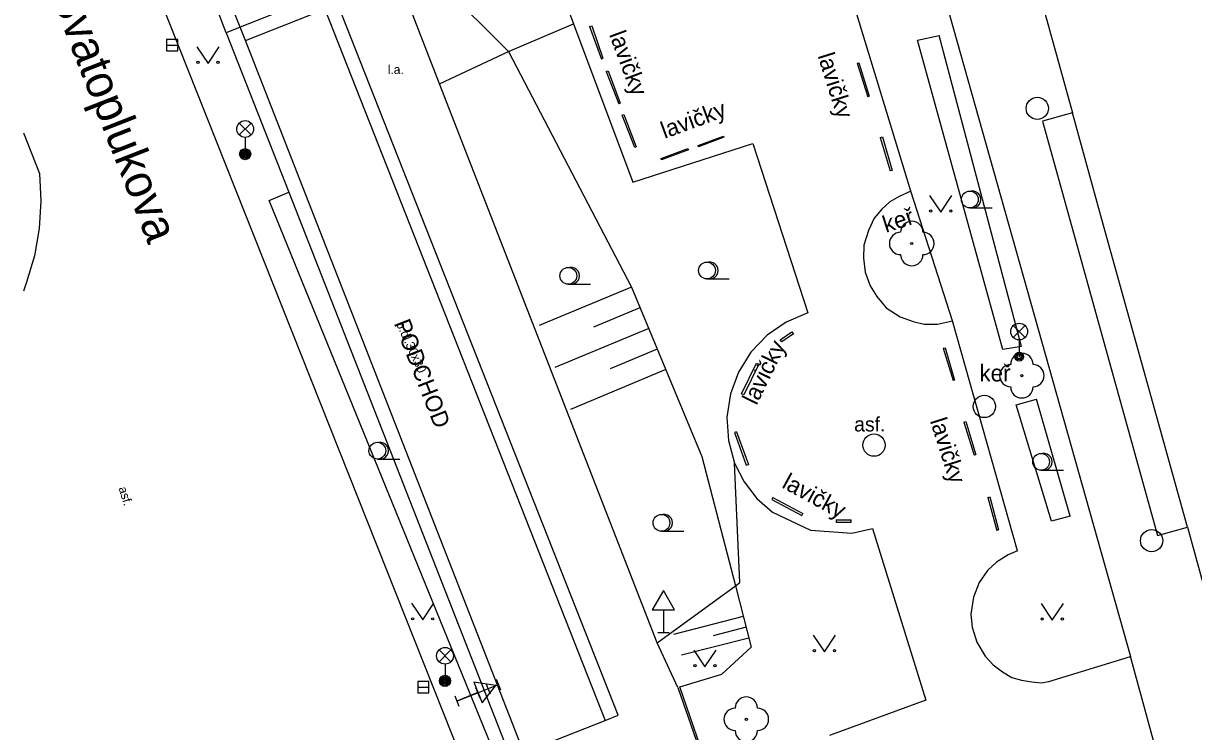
# Model space of a CAD drawing. Extents: x -595546 to -593986, y -1160845 to -1159202.
# Drawn here: x -595539.6 to -595487.2, y -1160276.7 to -1160245 of the extents above; entities that cross this region are included whole.
import ezdxf

# ---------------------------------------------------------------- set-up
doc = ezdxf.new("R2010")
doc.units = 0
for name, color, linetype in [('Level 22', 7, 'Continuous'), ('Level 25', 7, 'Continuous'), ('Level 27', 7, 'Continuous'), ('Level 33', 7, 'Continuous'), ('Level 34', 7, 'Continuous'), ('Level 36', 7, 'Continuous'), ('Nazvy ulic', 7, 'Continuous'), ('Specificka linie pasportu komunikaci', 7, 'Continuous'), ('TM - budovy zdene_ betonove - VP', 7, 'Continuous'), ('TM - chodniky - NP', 7, 'Continuous'), ('TM - chodniky - VP', 7, 'Continuous'), ('TM - horni hrana svahu', 7, 'Continuous'), ('TM - hranice souvisleho porostu (skupiny stromu_ kere)', 7, 'Continuous'), ('TM - komunikace - VP', 7, 'Continuous'), ('TM - lavicka', 7, 'Continuous'), ('TM - podezdivka plotu - VP', 7, 'Continuous'), ('TM - pomocna konstrukcni linie', 7, 'Continuous'), ('TM - popis objektu', 7, 'Continuous'), ('TM - popis povrchu', 7, 'Continuous'), ('TM - popis zelene', 7, 'Continuous'), ('TM - poznamka', 7, 'Continuous'), ('TM - rozhrani ploch obecne - VP', 7, 'Continuous'), ('TM - srafovani', 7, 'Continuous'), ('TM - zed operna - VP', 7, 'Continuous')]:
    doc.layers.add(name, color=color, linetype=linetype)

msp = doc.modelspace()

# ---------------------------------------------------------------- linework, layer by layer
at = {"layer": 'Level 22'}
for centre in [(-595499.8, -1160254.87), (-595494.87, -1160260.79), (-595507.21, -1160276.18)]:
    msp.add_circle(centre, 0.05, dxfattribs=at)
for centre, start, end in [((-595499.8, -1160254.37), 0, 180), ((-595500.3, -1160254.87), 90, 270), ((-595499.3, -1160254.87), 270, 90), ((-595499.8, -1160255.37), 180, 0), ((-595494.87, -1160260.29), 0, 180), ((-595495.37, -1160260.79), 90, 270), ((-595494.37, -1160260.79), 270, 90), ((-595494.87, -1160261.29), 180, 0), ((-595507.21, -1160275.68), 0, 180), ((-595507.71, -1160276.18), 90, 270), ((-595506.71, -1160276.18), 270, 90), ((-595507.21, -1160276.68), 180, 0)]:
    msp.add_arc(centre, 0.5, start, end, dxfattribs=at)
at = {"layer": 'Level 25'}
for centre, radius in [((-595529.65, -1160250.87), 0.25), ((-595529.65, -1160250.87), 0.2), ((-595529.65, -1160250.87), 0.15), ((-595529.65, -1160250.87), 0.1), ((-595529.65, -1160250.87), 0.05), ((-595520.7, -1160274.46), 0.25), ((-595520.7, -1160274.46), 0.2), ((-595520.7, -1160274.46), 0.15), ((-595520.7, -1160274.46), 0.1), ((-595520.7, -1160274.46), 0.05)]:
    msp.add_circle(centre, radius, dxfattribs=at)
at = {"layer": 'Level 27'}
for p, q in [((-595533.17, -1160245.99), (-595532.67, -1160245.99)), ((-595521.92, -1160274.74), (-595521.42, -1160274.74))]:
    msp.add_line(p, q, dxfattribs=at)
for points in [[(-595533.17, -1160246.24), (-595532.67, -1160246.24), (-595532.67, -1160245.74), (-595533.17, -1160245.74)], [(-595521.92, -1160274.99), (-595521.42, -1160274.99), (-595521.42, -1160274.49), (-595521.92, -1160274.49)]]:
    msp.add_lwpolyline(points, close=True, dxfattribs=at)
for centre in [(-595494.18, -1160248.82), (-595496.55, -1160262.17), (-595501.49, -1160263.9), (-595489.06, -1160268.18)]:
    msp.add_circle(centre, 0.5, dxfattribs=at)
at = {"layer": 'Level 33'}
for p, q in [((-595529.915, -1160250.01), (-595529.385, -1160249.48)), ((-595529.915, -1160249.48), (-595529.385, -1160250.01)), ((-595529.65, -1160250.12), (-595529.65, -1160250.87)), ((-595495.255, -1160259.08), (-595494.725, -1160258.55)), ((-595495.255, -1160258.55), (-595494.725, -1160259.08)), ((-595494.99, -1160259.19), (-595494.99, -1160259.94)), ((-595520.965, -1160273.6), (-595520.435, -1160273.07)), ((-595520.965, -1160273.07), (-595520.435, -1160273.6)), ((-595520.7, -1160273.71), (-595520.7, -1160274.46)), ((-595520.17, -1160275.36), (-595518.311, -1160274.622)), ((-595519.333, -1160274.759), (-595519.148, -1160275.223)), ((-595518.868, -1160274.574), (-595518.684, -1160275.039)), ((-595518.403, -1160274.389), (-595518.219, -1160274.854)), ((-595520.262, -1160275.128), (-595520.078, -1160275.592))]:
    msp.add_line(p, q, dxfattribs=at)
for centre, radius in [((-595529.65, -1160249.745), 0.375), ((-595529.65, -1160250.87), 0.2), ((-595529.65, -1160250.87), 0.145), ((-595529.65, -1160250.87), 0.0876), ((-595494.99, -1160258.815), 0.375), ((-595494.99, -1160259.94), 0.2), ((-595494.99, -1160259.94), 0.145), ((-595494.99, -1160259.94), 0.0876), ((-595520.7, -1160273.335), 0.375), ((-595520.7, -1160274.46), 0.2), ((-595520.7, -1160274.46), 0.145), ((-595520.7, -1160274.46), 0.0876)]:
    msp.add_circle(centre, radius, dxfattribs=at)
at = {"layer": 'Level 34'}
for p, q in [((-595510.92, -1160271.272), (-595510.92, -1160272.29)), ((-595511.17, -1160272.29), (-595510.67, -1160272.29)), ((-595520.262, -1160275.128), (-595520.078, -1160275.592)), ((-595519.224, -1160274.984), (-595520.17, -1160275.36))]:
    msp.add_line(p, q, dxfattribs=at)
for points in [[(-595511.42, -1160271.272), (-595510.42, -1160271.272), (-595510.92, -1160270.406)], [(-595519.408, -1160274.52), (-595519.039, -1160275.449), (-595518.419, -1160274.665)]]:
    msp.add_lwpolyline(points, close=True, dxfattribs=at)
at = {"layer": 'Level 36'}
for p, q in [((-595497.2, -1160253.275), (-595496.2, -1160253.275)), ((-595515.18, -1160256.695), (-595514.18, -1160256.695)), ((-595508.97, -1160256.455), (-595507.97, -1160256.455)), ((-595523.73, -1160264.525), (-595522.73, -1160264.525)), ((-595494.01, -1160265.025), (-595493.01, -1160265.025)), ((-595511.01, -1160267.755), (-595510.01, -1160267.755))]:
    msp.add_line(p, q, dxfattribs=at)
for points in [[(-595531.81, -1160246.06), (-595531.31, -1160246.81), (-595530.81, -1160246.06)], [(-595499, -1160252.72), (-595498.5, -1160253.47), (-595498, -1160252.72)], [(-595522.2, -1160270.98), (-595521.7, -1160271.73), (-595521.2, -1160270.98)], [(-595494.01, -1160270.99), (-595493.51, -1160271.74), (-595493.01, -1160270.99)], [(-595504.21, -1160272.41), (-595503.71, -1160273.16), (-595503.21, -1160272.41)], [(-595509.56, -1160273.08), (-595509.06, -1160273.83), (-595508.56, -1160273.08)]]:
    msp.add_lwpolyline(points, dxfattribs=at)
for centre, radius in [((-595531.76, -1160246.76), 0.05), ((-595530.861, -1160246.76), 0.05), ((-595497.2, -1160252.9), 0.375), ((-595498.95, -1160253.42), 0.05), ((-595498.051, -1160253.42), 0.05), ((-595508.97, -1160256.08), 0.375), ((-595515.18, -1160256.32), 0.375), ((-595523.73, -1160264.15), 0.375), ((-595494.01, -1160264.65), 0.375), ((-595511.01, -1160267.38), 0.375), ((-595522.15, -1160271.68), 0.05), ((-595521.251, -1160271.68), 0.05), ((-595493.96, -1160271.69), 0.05), ((-595493.061, -1160271.69), 0.05), ((-595504.16, -1160273.11), 0.05), ((-595503.261, -1160273.11), 0.05), ((-595509.51, -1160273.78), 0.05), ((-595508.611, -1160273.78), 0.05)]:
    msp.add_circle(centre, radius, dxfattribs=at)
for centre in [(-595497.075, -1160252.9), (-595508.845, -1160256.08), (-595515.055, -1160256.32), (-595523.605, -1160264.15), (-595493.885, -1160264.65), (-595510.885, -1160267.38)]:
    msp.add_arc(centre, 0.375, 260.4059, 99.5941, dxfattribs=at)
at = {"layer": 'Specificka linie pasportu komunikaci'}
for points in [[(-595487.46, -1160267.58), (-595491.21, -1160254.07), (-595492.61, -1160249.02)], [(-595497.98, -1160258.34), (-595498.488, -1160256.755), (-595499.84, -1160252.53)], [(-595488.38, -1160279.33), (-595490.01, -1160273.36)]]:
    msp.add_lwpolyline(points, dxfattribs=at)
at = {"layer": 'TM - budovy zdene_ betonove - VP'}
for points in [[(-595493.98, -1160244.06), (-595492.61, -1160249.02)], [(-595492.61, -1160249.02), (-595493.95, -1160249.4)], [(-595493.95, -1160249.4), (-595488.8, -1160267.95)], [(-595488.8, -1160267.95), (-595487.46, -1160267.58)], [(-595487.46, -1160267.58), (-595486.01, -1160272.85)]]:
    msp.add_lwpolyline(points, dxfattribs=at)
at = {"layer": 'TM - chodniky - NP'}
for points in [[(-595529.87, -1160245.18), (-595532.21, -1160239.27)], [(-595529.63, -1160245.78), (-595529.87, -1160245.18)]]:
    msp.add_lwpolyline(points, dxfattribs=at)
at = {"layer": 'TM - chodniky - VP'}
for points in [[(-595500.77, -1160235.2), (-595490.01, -1160273.36)], [(-595517.54, -1160238.05), (-595514.94, -1160245.03)], [(-595530.5, -1160245.43), (-595532.76, -1160239.49)], [(-595520.94, -1160247.72), (-595523.8, -1160240.35)], [(-595499.84, -1160252.53), (-595502.96, -1160242.29)], [(-595514.94, -1160245.03), (-595512.29, -1160252.13), (-595506.91, -1160250.4), (-595504.45, -1160257.98)], [(-595511.2, -1160272.76), (-595520.94, -1160247.72)], [(-595499.84, -1160252.53), (-595500.36, -1160252.76), (-595500.78, -1160253.01), (-595501.14, -1160253.34), (-595501.48, -1160253.74), (-595501.74, -1160254.29), (-595501.94, -1160254.95), (-595501.96, -1160255.53), (-595501.89, -1160256.16), (-595501.67, -1160256.76), (-595501.36, -1160257.25), (-595500.94, -1160257.75), (-595500.32, -1160258.15), (-595499.74, -1160258.36), (-595499.25, -1160258.48), (-595498.65, -1160258.48), (-595497.98, -1160258.34)], [(-595504.45, -1160257.98), (-595505.42, -1160258.39), (-595506.28, -1160258.98), (-595507.01, -1160259.74), (-595507.56, -1160260.63), (-595507.92, -1160261.61), (-595508.08, -1160262.65), (-595508.01, -1160263.7), (-595507.74, -1160264.71)], [(-595495.06, -1160268.63), (-595497.98, -1160258.34)], [(-595507.74, -1160264.71), (-595507.31, -1160265.55), (-595506.74, -1160266.29), (-595506.03, -1160266.91), (-595504.34, -1160267.71), (-595502.48, -1160267.84), (-595501.56, -1160267.64)], [(-595501.56, -1160267.64), (-595499.17, -1160275.32), (-595503.49, -1160276.91)], [(-595495.06, -1160268.63), (-595495.49, -1160268.82), (-595496, -1160269.14), (-595496.41, -1160269.51), (-595496.78, -1160270.06), (-595497.04, -1160270.71), (-595497.16, -1160271.47), (-595497.09, -1160272.05), (-595496.88, -1160272.72), (-595496.51, -1160273.35), (-595496.15, -1160273.74), (-595495.74, -1160274.06), (-595495.32, -1160274.3), (-595494.89, -1160274.42), (-595494.43, -1160274.5), (-595494, -1160274.54), (-595493.66, -1160274.48)], [(-595510.27, -1160274.76), (-595511.2, -1160272.76)], [(-595493.66, -1160274.48), (-595490.01, -1160273.36)], [(-595510.27, -1160274.76), (-595508.87, -1160278.78)]]:
    msp.add_lwpolyline(points, dxfattribs=at)
at = {"layer": 'TM - horni hrana svahu'}
for points in [[(-595523.8, -1160240.35), (-595517.86, -1160246.27)], [(-595517.86, -1160246.27), (-595512.35, -1160256.83), (-595509.2, -1160264.41), (-595507.7, -1160270.2)], [(-595507.7, -1160270.2), (-595506.99, -1160272.95), (-595508.3, -1160274.16)]]:
    msp.add_lwpolyline(points, dxfattribs=at)
at = {"layer": 'TM - hranice souvisleho porostu (skupiny stromu_ kere)'}
for points in [[(-595517.86, -1160246.27), (-595514.94, -1160245.03)], [(-595494.88, -1160259.48), (-595495.72, -1160259.62), (-595499.55, -1160245.76), (-595498.57, -1160245.55)], [(-595494.88, -1160259.48), (-595498.57, -1160245.55)], [(-595520.94, -1160247.72), (-595517.86, -1160246.27)], [(-595528.58, -1160252.94), (-595527.7, -1160252.58)], [(-595514.08, -1160288.52), (-595528.58, -1160252.94)], [(-595492.71, -1160267.08), (-595493.54, -1160267.3), (-595495.13, -1160262.09), (-595494.22, -1160261.84)], [(-595492.71, -1160267.08), (-595494.22, -1160261.84)]]:
    msp.add_lwpolyline(points, dxfattribs=at)
at = {"layer": 'TM - komunikace - VP'}
for points in [[(-595503.44, -1160319.53), (-595534.32, -1160241.75)], [(-595539.58, -1160249.921), (-595538.86, -1160251.73)], [(-595538.86, -1160251.73), (-595538.8, -1160252.96), (-595538.87, -1160254.2), (-595539.09, -1160255.42), (-595539.44, -1160256.6)], [(-595539.44, -1160256.6), (-595539.58, -1160257.005)]]:
    msp.add_lwpolyline(points, dxfattribs=at)
at = {"layer": 'TM - lavicka'}
for points in [[(-595514.23, -1160245.16), (-595513.69, -1160246.61)], [(-595502.24, -1160246.8), (-595501.77, -1160248.3)], [(-595513.49, -1160247.17), (-595512.91, -1160248.62)], [(-595512.2, -1160250.57), (-595512.77, -1160249.13)], [(-595508.21, -1160250.11), (-595509.35, -1160250.55)], [(-595501.21, -1160250.13), (-595500.76, -1160251.62)], [(-595509.8, -1160250.68), (-595511, -1160251.12)], [(-595505.1, -1160258.92), (-595505.62, -1160259.28)], [(-595498.39, -1160259.56), (-595497.94, -1160261.01)], [(-595506.65, -1160260.28), (-595507.32, -1160261.65)], [(-595497.47, -1160262.87), (-595497, -1160264.35)], [(-595507.65, -1160263.3), (-595507.11, -1160264.77)], [(-595506.02, -1160266.24), (-595504.68, -1160266.97)], [(-595496.4, -1160266.25), (-595495.99, -1160267.72)], [(-595503.18, -1160267.24), (-595502.52, -1160267.24)]]:
    msp.add_lwpolyline(points, dxfattribs=at)
at = {"layer": 'TM - podezdivka plotu - VP'}
for points in [[(-595529.63, -1160245.78), (-595526.08, -1160244.38)], [(-595526.08, -1160244.38), (-595513.53, -1160276.23)], [(-595517.17, -1160277.67), (-595529.63, -1160245.78)], [(-595513.53, -1160276.23), (-595512.95, -1160276)]]:
    msp.add_lwpolyline(points, dxfattribs=at)
at = {"layer": 'TM - pomocna konstrukcni linie'}
for points in [[(-595514.23, -1160245.16), (-595514.13, -1160245.13), (-595513.63, -1160246.57), (-595513.69, -1160246.61)], [(-595502.24, -1160246.8), (-595502.17, -1160246.78), (-595501.71, -1160248.28), (-595501.77, -1160248.3)], [(-595513.49, -1160247.17), (-595513.4, -1160247.14), (-595512.85, -1160248.59), (-595512.91, -1160248.62)], [(-595512.77, -1160249.13), (-595512.69, -1160249.1), (-595512.14, -1160250.54), (-595512.2, -1160250.57)], [(-595509.35, -1160250.55), (-595509.37, -1160250.49), (-595508.23, -1160250.06), (-595508.21, -1160250.11)], [(-595501.21, -1160250.13), (-595501.11, -1160250.1), (-595500.68, -1160251.6), (-595500.76, -1160251.62)], [(-595511, -1160251.12), (-595511.02, -1160251.06), (-595509.82, -1160250.62), (-595509.8, -1160250.68)], [(-595505.62, -1160259.28), (-595505.69, -1160259.19), (-595505.17, -1160258.83), (-595505.1, -1160258.92)], [(-595498.39, -1160259.56), (-595498.31, -1160259.54), (-595497.88, -1160260.99), (-595497.94, -1160261.01)], [(-595507.32, -1160261.65), (-595507.43, -1160261.6), (-595506.75, -1160260.23), (-595506.65, -1160260.28)], [(-595497.47, -1160262.87), (-595497.38, -1160262.84), (-595496.93, -1160264.33), (-595497, -1160264.35)], [(-595507.65, -1160263.3), (-595507.74, -1160263.33), (-595507.21, -1160264.8), (-595507.11, -1160264.77)], [(-595506.02, -1160266.24), (-595506.06, -1160266.33), (-595504.72, -1160267.05), (-595504.68, -1160266.97)], [(-595496.4, -1160266.25), (-595496.3, -1160266.22), (-595495.91, -1160267.69), (-595495.99, -1160267.72)], [(-595503.18, -1160267.24), (-595503.18, -1160267.35), (-595502.52, -1160267.35), (-595502.52, -1160267.24)]]:
    msp.add_lwpolyline(points, dxfattribs=at)
at = {"layer": 'TM - rozhrani ploch obecne - VP'}
for points in [[(-595507.7, -1160270.2), (-595507.5, -1160270.06), (-595507.74, -1160264.71)], [(-595511.2, -1160272.76), (-595507.7, -1160270.2)], [(-595517.17, -1160277.67), (-595513.53, -1160276.23)]]:
    msp.add_lwpolyline(points, dxfattribs=at)
at = {"layer": 'TM - srafovani'}
for points in [[(-595512.35, -1160256.83), (-595516.49, -1160258.55)], [(-595511.97, -1160257.75), (-595514.05, -1160258.62)], [(-595511.58, -1160258.68), (-595515.78, -1160260.42)], [(-595511.2, -1160259.6), (-595513.31, -1160260.48)], [(-595510.82, -1160260.52), (-595515.08, -1160262.3)], [(-595507.35, -1160271.57), (-595510.47, -1160272.38)], [(-595507.22, -1160272.05), (-595508.7, -1160272.44)], [(-595507.1, -1160272.54), (-595510.11, -1160273.31)]]:
    msp.add_lwpolyline(points, dxfattribs=at)
at = {"layer": 'TM - zed operna - VP'}
for points in [[(-595526.31, -1160243.77), (-595529.87, -1160245.18)], [(-595512.95, -1160276), (-595525.74, -1160243.54)], [(-595529.87, -1160245.18), (-595530.5, -1160245.43)], [(-595530.5, -1160245.43), (-595527.7, -1160252.58)], [(-595527.7, -1160252.58), (-595517.76, -1160277.94)], [(-595510.18, -1160274.73), (-595508.3, -1160274.16)], [(-595508.8, -1160278.75), (-595510.18, -1160274.73)]]:
    msp.add_lwpolyline(points, dxfattribs=at)

# ---------------------------------------------------------------- texts
at = {"layer": 'Nazvy ulic'}
msp.add_text('Svatoplukova', height=1.5, rotation=291.3834, dxfattribs=at).set_placement((-595538.376, -1160243.739))
at = {"layer": 'TM - popis objektu'}
msp.add_text('PODCHOD', height=0.75, rotation=291.36, dxfattribs=at).set_placement((-595523, -1160258.44))
msp.add_text('PODCHOD', height=0.75, rotation=291.36, dxfattribs=at).set_placement((-595523, -1160258.44))
at = {"layer": 'TM - popis povrchu'}
for s, height, p in [('l.a.', 0.4, (-595523.26, -1160247.28)), ('asf.', 0.65, (-595502.38, -1160263.29))]:
    msp.add_text(s, height=height, dxfattribs=at).set_placement(p)
for s, rotation, p in [('b.dl.30x30', 294.4427, (-595522.9, -1160258.47)), ('asf.', 288.0043, (-595535.33, -1160265.83))]:
    msp.add_text(s, height=0.4, rotation=rotation, dxfattribs=at).set_placement(p)
at = {"layer": 'TM - popis zelene'}
msp.add_text('keř', height=0.75, rotation=17.8258, dxfattribs=at).set_placement((-595500.96, -1160254.4))
msp.add_text('keř', height=0.75, dxfattribs=at).set_placement((-595496.77, -1160261.05))
at = {"layer": 'TM - poznamka'}
for rotation, p in [(290.426, (-595513.36, -1160245.51)), (287.3975, (-595504.02, -1160246.46)), (20.1363, (-595510.87, -1160250.19)), (63.939, (-595506.75, -1160262.15)), (287.6182, (-595498.99, -1160262.81)), (331.4195, (-595505.66, -1160265.78))]:
    msp.add_text('lavičky', height=0.75, rotation=rotation, dxfattribs=at).set_placement(p)

doc.saveas('drawing.dxf')
